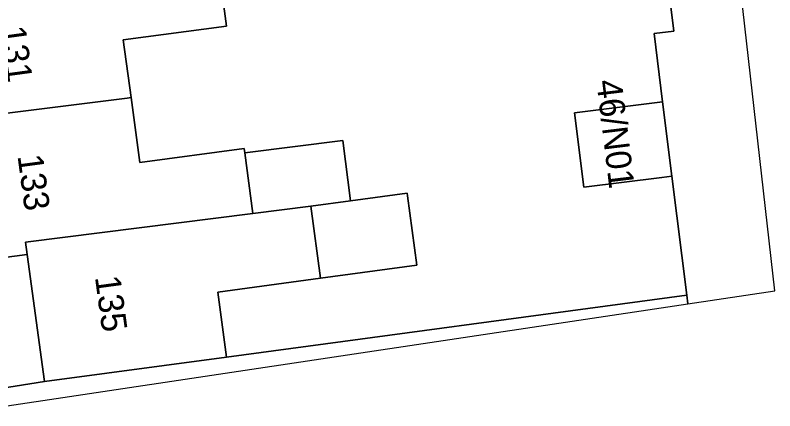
# Model space of a CAD drawing. Extents: x 163147 to 163550, y 380933 to 381639.
# Drawn here: x 163519.95 to 163549.87, y 381127.28 to 381142.86 of the extents above; entities that cross this region are included whole.
import ezdxf

# ---------------------------------------------------------------- set-up
doc = ezdxf.new("R2010")
doc.units = 0
for name, color, linetype in [('IMGEO_Erf', 7, 'Continuous'), ('IMGEO_Pand', 7, 'Continuous'), ('IMGEO_Pand_nummerreeks', 7, 'Continuous'), ('IMGEO_Rijbaan_lokaal_open', 7, 'Continuous'), ('IMGEO_Voetpad_open', 7, 'Continuous')]:
    doc.layers.add(name, color=color, linetype=linetype)

msp = doc.modelspace()

# ---------------------------------------------------------------- linework, layer by layer
at = {"layer": 'IMGEO_Erf'}
msp.add_lwpolyline([(163527.903, 381145.205), (163528.276, 381142.433), (163524.21, 381141.886), (163524.515, 381139.614), (163524.858, 381137.062), (163528.97, 381137.615), (163528.993, 381137.442), (163532.862, 381137.927), (163533.16, 381135.545), (163535.387, 381135.845), (163535.401, 381135.745), (163535.769, 381133.008), (163531.979, 381132.498), (163527.931, 381131.953), (163528.275, 381129.394), (163546.401, 381131.833), (163545.817, 381136.522), (163545.421, 381136.469), (163542.344, 381136.09), (163541.98, 381139.014), (163545.032, 381139.402), (163545.453, 381139.446), (163545.122, 381142.143), (163545.895, 381142.238), (163545.254, 381147.457)], dxfattribs=at)
msp.add_lwpolyline([(163520.43, 381133.44), (163517.529, 381133.05), (163518.211, 381127.971), (163521.104, 381128.429)], close=True, dxfattribs=at)
at = {"layer": 'IMGEO_Pand'}
for points in [[(163517.313, 381138.711), (163524.359, 381139.594), (163524.515, 381139.614), (163524.21, 381141.886), (163528.276, 381142.433), (163527.903, 381145.205), (163527.724, 381145.183), (163516.63, 381143.791)], [(163528.993, 381137.442), (163528.97, 381137.615), (163524.858, 381137.062), (163524.515, 381139.614), (163524.359, 381139.594), (163517.313, 381138.711), (163516.787, 381138.564), (163517.46, 381133.562), (163517.529, 381133.05), (163520.43, 381133.44), (163520.365, 381133.926), (163529.314, 381135.053)], [(163545.032, 381139.402), (163541.98, 381139.014), (163542.344, 381136.09), (163545.421, 381136.469), (163545.817, 381136.522), (163545.453, 381139.446)], [(163528.993, 381137.442), (163529.314, 381135.053), (163531.597, 381135.335), (163533.16, 381135.545), (163532.862, 381137.927)], [(163533.16, 381135.545), (163531.597, 381135.335), (163531.979, 381132.498), (163535.769, 381133.008), (163535.401, 381135.745), (163535.387, 381135.845)], [(163531.979, 381132.498), (163531.597, 381135.335), (163529.314, 381135.053), (163520.365, 381133.926), (163520.43, 381133.44), (163521.104, 381128.429), (163528.275, 381129.394), (163527.931, 381131.953)]]:
    msp.add_lwpolyline(points, close=True, dxfattribs=at)
at = {"layer": 'IMGEO_Rijbaan_lokaal_open'}
msp.add_lwpolyline([(163545.254, 381147.457), (163545.895, 381142.238), (163545.122, 381142.143), (163545.453, 381139.446), (163545.817, 381136.522), (163546.401, 381131.833), (163546.445, 381131.489), (163549.87, 381132.002), (163529.08, 381315.546)], dxfattribs=at)
at = {"layer": 'IMGEO_Voetpad_open'}
msp.add_lwpolyline([(163518.312, 381127.276), (163546.445, 381131.489), (163546.401, 381131.833), (163528.275, 381129.394), (163521.104, 381128.429), (163518.211, 381127.971), (163518.295, 381127.348)], close=True, dxfattribs=at)

# ---------------------------------------------------------------- texts
at = {"layer": 'IMGEO_Pand_nummerreeks'}
for s, rotation, p in [('131', 277.6609, (163519.362, 381142.381)), ('46/N01', 276.8982, (163542.84, 381140.273)), ('133', 277.6602, (163520.043, 381137.32)), ('135', 277.6602, (163523.093, 381132.546))]:
    msp.add_text(s, height=1, rotation=rotation, dxfattribs=at).set_placement(p)

doc.saveas('drawing.dxf')
